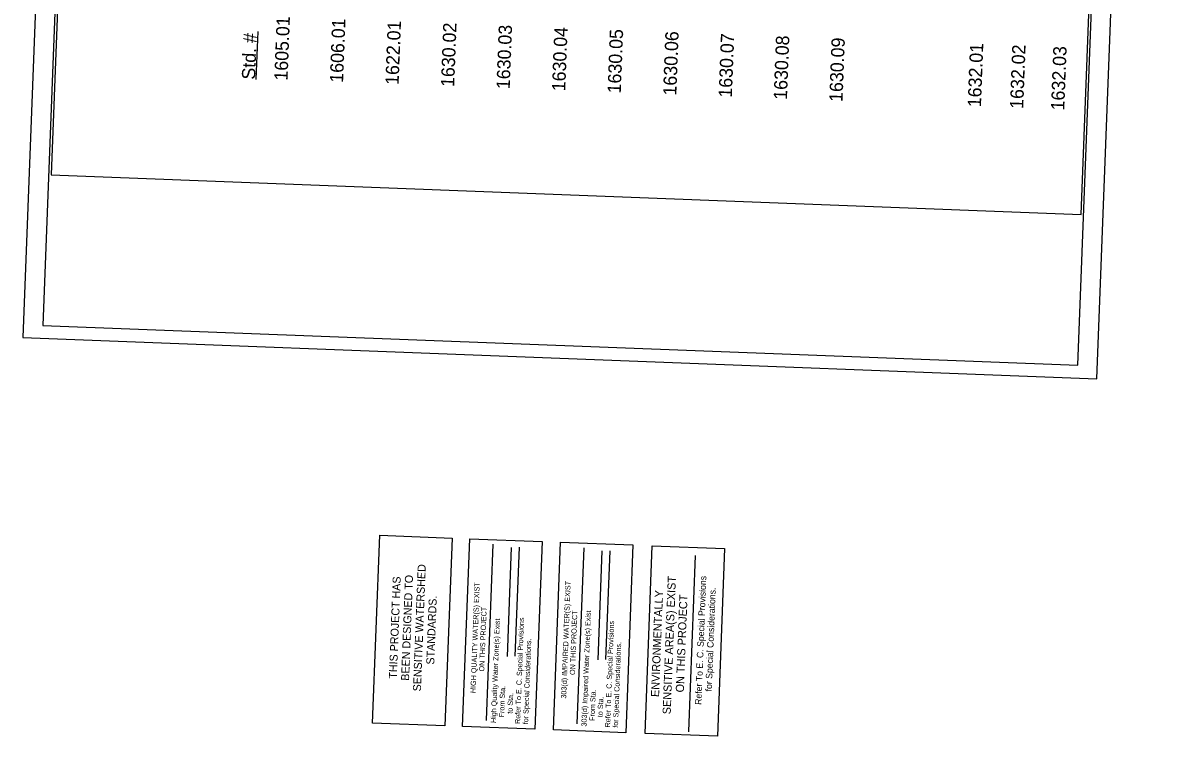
# Model space of a CAD drawing. Extents: x 1654773 to 2116434, y 680831 to 888488.
# Drawn here: x 2109739 to 2115533, y 690405 to 694040 of the extents above; entities that cross this region are included whole.
import ezdxf

# ---------------------------------------------------------------- set-up
doc = ezdxf.new("R2010")
doc.units = 0
for name, color, linetype in [('EC Title Sheet CELL', 7, 'Continuous'), ('Scratch_Level_6', 7, 'Continuous'), ('Sheet Plot Border Inside CELL', 7, 'Continuous'), ('Sheet Plot Border Outside CELL', 7, 'Continuous')]:
    doc.layers.add(name, color=color, linetype=linetype)

msp = doc.modelspace()

# ---------------------------------------------------------------- linework, layer by layer
at = {"layer": 'EC Title Sheet CELL'}
for p, q in [((2110928.9, 693750.1), (2110938, 693995)), ((2112207.6, 690812.1), (2112228.9, 691367.2)), ((2112247.5, 690813.2), (2112268.9, 691368.1)), ((2112669.8, 690794.4), (2112691.1, 691349.4)), ((2112709.7, 690795.5), (2112731.1, 691350.4))]:
    msp.add_line(p, q, dxfattribs=at)
for points in [[(2111521.1, 690472.8), (2111557.8, 691429.1), (2111926.3, 691414.9), (2111889.6, 690458.7)], [(2111979.7, 690455.2), (2112016.4, 691411.5), (2112384.9, 691397.3), (2112348.2, 690441.1)], [(2112441.9, 690437.5), (2112478.6, 691393.8), (2112847.1, 691379.6), (2112810.4, 690423.4)], [(2112909, 690419.6), (2112945.7, 691375.8), (2113314.2, 691361.6), (2113277.5, 690405.4)]]:
    msp.add_lwpolyline(points, close=True, dxfattribs=at)
for points in [[(2112101.7, 690485.8), (2112101.8, 690487.5), (2112136.2, 691383.3)], [(2112563.9, 690468), (2112564, 690469.8), (2112598.4, 691365.6)], [(2113131.6, 690428.7), (2113131.6, 690430.3), (2113166, 691326.3)]]:
    msp.add_lwpolyline(points, dxfattribs=at)
at = {"layer": 'Scratch_Level_6'}
for p, q in [((2109883.7, 693264.2), (2109883.7, 693264.2)), ((2115129.9, 693062.9), (2115129.9, 693062.9))]:
    msp.add_line(p, q, dxfattribs=at)
msp.add_lwpolyline([(2110171.4, 700758.7), (2109883.7, 693264.2), (2115129.9, 693062.9), (2115417.5, 700557.4)], close=True, dxfattribs=at)
at = {"layer": 'Sheet Plot Border Inside CELL'}
msp.add_lwpolyline([(2115112.9, 692295.5), (2115432.4, 700619.3), (2110161.3, 700821.7), (2109841.8, 692497.8)], close=True, dxfattribs=at)
at = {"layer": 'Sheet Plot Border Outside CELL'}
msp.add_lwpolyline([(2115210.4, 692226.7), (2115533.2, 700638), (2110062.2, 700848), (2109739.4, 692436.7)], close=True, dxfattribs=at)

# ---------------------------------------------------------------- texts
at = {"layer": 'EC Title Sheet CELL'}
for s, height, p in [('1605.01', 67.74, (2111087.9, 693743.9)), ('1606.01', 67.74, (2111370.8, 693733.1)), ('1622.01', 67.74, (2111653.7, 693722.2)), ('Std. #', 67.83, (2110922.8, 693749.1)), ('1630.02', 67.74, (2111936.6, 693711.4)), ('1630.03', 67.74, (2112219.5, 693700.5)), ('1630.04', 67.74, (2112502.3, 693689.7)), ('1630.05', 67.74, (2112785.2, 693678.8)), ('1630.06', 67.74, (2113068.1, 693667.9)), ('1630.07', 67.74, (2113351, 693657.1)), ('1630.08', 67.74, (2113631.6, 693646.3)), ('1630.09', 67.74, (2113914.5, 693635.5)), ('1632.01', 67.74, (2114619.7, 693608.4)), ('1632.02', 67.74, (2114835, 693600.1)), ('1632.03', 67.74, (2115044.1, 693592.1)), ('SENSITIVE WATERSHED', 40.763, (2111767.4, 690633.3)), ('THIS PROJECT HAS', 40.763, (2111644.8, 690697.9)), ('BEEN DESIGNED TO ', 40.763, (2111706.9, 690687.7)), ('SENSITIVE AREA(S) EXIST', 41.397, (2113039.5, 690516.9)), ('Refer To E. C. Special Provisions', 33.117, (2113196.1, 690564.8)), ('    HIGH QUALITY WATER(S) EXIST', 26.494, (2112044, 690584)), ('   303(d) IMPAIRED WATER(S) EXIST', 26.494, (2112506.2, 690566.2)), ('ENVIRONMENTALLY ', 41.397, (2112980.2, 690604.5)), ('for Special Considerations.', 33.117, (2113248.9, 690633.3)), ('STANDARDS.', 40.76, (2111835.1, 690769.9)), ('ON THIS PROJECT', 41.397, (2113106.5, 690628)), ('               ON THIS PROJECT', 26.494, (2112084.1, 690582.4)), ('               ON THIS PROJECT', 26.494, (2112546.2, 690564.7)), ('303(d) Impaired Water Zone(s) Exist', 26.494, (2112610.7, 690454.5)), ('High Quality Water Zone(s) Exist', 26.494, (2112149.3, 690472.2)), ('Refer To E. C. Special Provisions', 26.494, (2112272.4, 690467.5)), ('Refer To E. C. Special Provisions', 26.494, (2112730.9, 690449.8)), ('for Special Considerations.', 26.494, (2112313.1, 690465.9)), ('for Special Considerations.', 26.494, (2112771, 690448.3)), ('   From Sta.                      ', 26.494, (2112190, 690470.7)), ('   From Sta.                      ', 26.494, (2112650.8, 690452.9)), ('     to Sta.', 26.494, (2112231.6, 690469.1)), ('     to Sta.', 26.494, (2112690.9, 690451.4))]:
    msp.add_text(s, height=height, rotation=87.80201, dxfattribs=at).set_placement(p)

doc.saveas('drawing.dxf')
